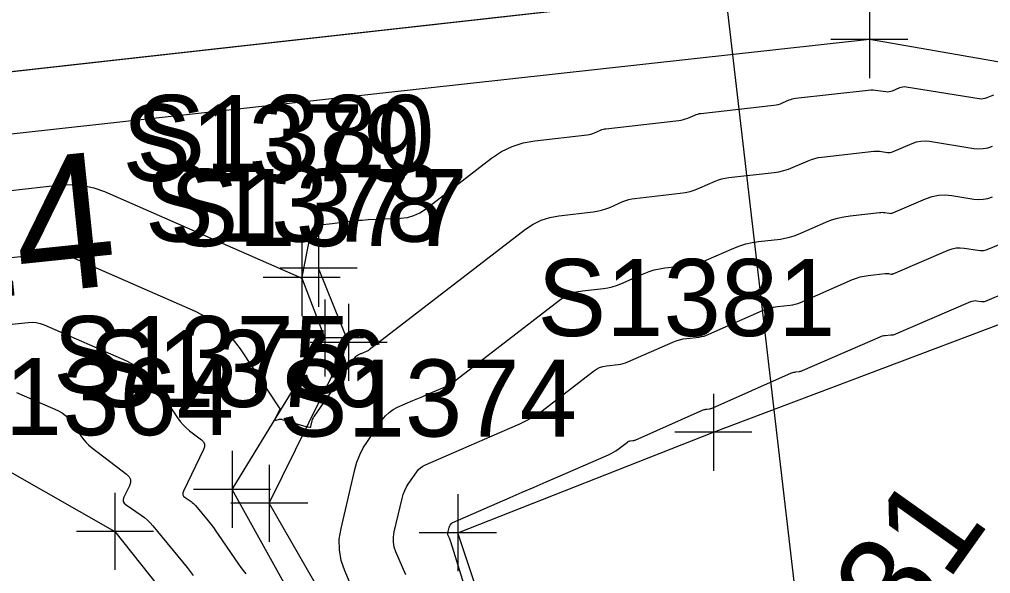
# Model space of a CAD drawing. Extents: x 816928 to 825690, y 436959 to 448212.
# Drawn here: x 818841.5 to 818891.9, y 445163.6 to 445192.4 of the extents above; entities that cross this region are included whole.
import ezdxf

# ---------------------------------------------------------------- set-up
doc = ezdxf.new("R2010")
doc.units = 0
for name, color, linetype in [('SURVEY - CONTOURS - Index with Text', 7, 'Continuous'), ('SURVEY - CONTOURS - Intermediate with optional Text', 7, 'Continuous'), ('SURVEY - DRAINAGE - Bridge Hydraulic Data - Points - Locators', 7, 'Continuous'), ('SURVEY - DRAINAGE - Bridge Hydraulic Data - Points - Numbers', 7, 'Continuous'), ('SURVEY - DRAINAGE - Bridge Hydraulic Data with Text', 7, 'Continuous'), ('SURVEY - DRAINAGE - Bridges Text', 7, 'Continuous'), ('SURVEY - DRAINAGE - Natural Features', 7, 'Continuous'), ('SURVEY - DTM - Breaklines', 7, 'Continuous'), ('SURVEY - DTM - Breaklines - Points - Locators', 7, 'Continuous'), ('SURVEY - DTM - Breaklines - Points - Numbers', 7, 'Continuous'), ('SURVEY - PROPERTY - Parcels', 7, 'Continuous'), ('SURVEY - PROPERTY - ROW Lines', 7, 'Continuous')]:
    doc.layers.add(name, color=color, linetype=linetype)

msp = doc.modelspace()

# ---------------------------------------------------------------- linework, layer by layer
at = {"layer": 'SURVEY - CONTOURS - Index with Text'}
msp.add_lwpolyline([(818840.893, 445183.514), (818843.638, 445183.823), (818844.22, 445183.851), (818844.791, 445183.803), (818845.35, 445183.679), (818845.898, 445183.48), (818856.103, 445179.004), (818856.108, 445179.002), (818856.112, 445178.999), (818856.115, 445178.996), (818856.118, 445178.992), (818856.127, 445178.978), (818856.129, 445178.976), (818856.131, 445178.975), (818856.133, 445178.976), (818856.136, 445178.978), (818856.143, 445178.987), (818856.145, 445178.989), (818856.146, 445178.992), (818856.147, 445178.994), (818856.148, 445178.996), (818856.153, 445179.016), (818856.154, 445179.021), (818856.156, 445179.025), (818856.157, 445179.029), (818856.157, 445179.034), (818856.619, 445181.334), (818856.676, 445181.503), (818856.772, 445181.63), (818856.907, 445181.716), (818857.081, 445181.759), (818857.711, 445181.831), (818857.845, 445181.847), (818857.98, 445181.862), (818858.115, 445181.878), (818858.25, 445181.893), (818858.966, 445181.976), (818859.119, 445181.992), (818859.273, 445182.005), (818859.427, 445182.016), (818859.581, 445182.024), (818861.271, 445182.098), (818861.623, 445182.139), (818861.957, 445182.232), (818862.272, 445182.377), (818862.569, 445182.572), (818865.992, 445185.214), (818866.506, 445185.558), (818867.051, 445185.825), (818867.628, 445186.013), (818868.236, 445186.122), (818870.946, 445186.428), (818871.047, 445186.443), (818871.147, 445186.466), (818871.244, 445186.496), (818871.34, 445186.534), (818871.649, 445186.67), (818871.715, 445186.697), (818871.784, 445186.718), (818871.853, 445186.734), (818871.924, 445186.745), (818875.716, 445187.172), (818875.834, 445187.19), (818875.949, 445187.216), (818876.062, 445187.251), (818876.173, 445187.295), (818876.531, 445187.454), (818876.609, 445187.485), (818876.688, 445187.509), (818876.769, 445187.528), (818876.852, 445187.54), (818880.638, 445187.966), (818880.754, 445187.984), (818880.868, 445188.01), (818880.979, 445188.044), (818881.088, 445188.087), (818881.44, 445188.241), (818881.517, 445188.271), (818881.594, 445188.295), (818881.674, 445188.313), (818881.755, 445188.325), (818885.54, 445188.75), (818885.666, 445188.76), (818885.792, 445188.762), (818885.918, 445188.754), (818886.043, 445188.739), (818886.452, 445188.674), (818886.539, 445188.666), (818886.625, 445188.671), (818886.709, 445188.688), (818886.791, 445188.717), (818887.171, 445188.88), (818887.253, 445188.909), (818887.336, 445188.925), (818887.422, 445188.93), (818887.508, 445188.922), (818891.297, 445188.312), (818891.405, 445188.302), (818891.511, 445188.307), (818891.615, 445188.327), (818891.718, 445188.363), (818892.05, 445188.502)], dxfattribs=at)
at = {"layer": 'SURVEY - CONTOURS - Intermediate with optional Text'}
for points in [[(818840.919, 445180.044), (818842.789, 445180.255), (818843.186, 445180.274), (818843.575, 445180.241), (818843.956, 445180.157), (818844.329, 445180.021), (818850.611, 445177.266), (818851.299, 445176.906), (818851.916, 445176.461), (818852.462, 445175.93), (818852.936, 445175.315), (818854.973, 445172.254), (818854.977, 445172.249), (818854.981, 445172.244), (818854.986, 445172.239), (818854.991, 445172.235), (818855.009, 445172.221), (818855.012, 445172.218), (818855.013, 445172.215), (818855.013, 445172.211), (818855.012, 445172.207), (818854.76, 445171.686), (818854.747, 445171.647), (818854.751, 445171.623), (818854.774, 445171.613), (818854.815, 445171.617), (818854.978, 445171.656), (818855.013, 445171.661), (818855.048, 445171.663), (818855.082, 445171.659), (818855.117, 445171.651), (818856.353, 445171.28), (818856.382, 445171.272), (818856.411, 445171.265), (818856.44, 445171.26), (818856.469, 445171.255), (818856.566, 445171.243), (818856.585, 445171.243), (818856.599, 445171.249), (818856.61, 445171.261), (818856.617, 445171.278), (818856.687, 445171.579), (818856.705, 445171.642), (818856.729, 445171.703), (818856.758, 445171.761), (818856.793, 445171.816), (818858.907, 445174.872), (818858.938, 445174.912), (818858.974, 445174.946), (818859.015, 445174.975), (818859.06, 445174.998), (818859.213, 445175.064), (818859.246, 445175.079), (818859.279, 445175.093), (818859.312, 445175.107), (818859.345, 445175.122), (818859.512, 445175.194), (818859.548, 445175.211), (818859.582, 445175.229), (818859.614, 445175.25), (818859.646, 445175.273), (818867.754, 445181.528), (818868.148, 445181.792), (818868.566, 445181.996), (818869.008, 445182.141), (818869.474, 445182.225), (818871.255, 445182.425), (818871.479, 445182.459), (818871.7, 445182.51), (818871.915, 445182.577), (818872.127, 445182.661), (818872.809, 445182.961), (818872.957, 445183.02), (818873.108, 445183.067), (818873.262, 445183.102), (818873.42, 445183.126), (818875.783, 445183.392), (818876.045, 445183.432), (818876.301, 445183.491), (818876.552, 445183.569), (818876.797, 445183.667), (818877.591, 445184.018), (818877.763, 445184.086), (818877.939, 445184.141), (818878.118, 445184.182), (818878.301, 445184.21), (818880.649, 445184.474), (818880.906, 445184.512), (818881.158, 445184.57), (818881.405, 445184.646), (818881.647, 445184.741), (818882.429, 445185.083), (818882.599, 445185.15), (818882.772, 445185.203), (818882.948, 445185.243), (818883.128, 445185.27), (818885.833, 445185.574), (818885.93, 445185.582), (818886.028, 445185.583), (818886.126, 445185.577), (818886.223, 445185.565), (818886.541, 445185.515), (818886.609, 445185.509), (818886.675, 445185.512), (818886.74, 445185.525), (818886.804, 445185.548), (818887.818, 445185.984), (818888.038, 445186.061), (818888.261, 445186.105), (818888.488, 445186.117), (818888.72, 445186.096), (818891.022, 445185.725), (818891.267, 445185.703), (818891.509, 445185.714), (818891.746, 445185.76), (818891.979, 445185.84)], [(818859.438, 445161.295), (818858.37, 445163.788), (818858.186, 445164.327), (818858.093, 445164.873), (818858.09, 445165.427), (818858.177, 445165.989), (818858.896, 445169.047), (818859.006, 445169.435), (818859.151, 445169.807), (818859.33, 445170.165), (818859.544, 445170.507), (818860.32, 445171.628), (818860.483, 445171.833), (818860.669, 445172.009), (818860.879, 445172.158), (818861.111, 445172.278), (818861.91, 445172.624), (818862.081, 445172.698), (818862.252, 445172.773), (818862.423, 445172.847), (818862.594, 445172.921), (818863.461, 445173.297), (818863.644, 445173.383), (818863.82, 445173.48), (818863.99, 445173.587), (818864.154, 445173.706), (818869.516, 445177.842), (818869.79, 445178.026), (818870.08, 445178.168), (818870.388, 445178.268), (818870.712, 445178.327), (818871.8, 445178.45), (818872.031, 445178.484), (818872.257, 445178.536), (818872.479, 445178.605), (818872.696, 445178.691), (818873.905, 445179.224), (818874.167, 445179.328), (818874.434, 445179.411), (818874.707, 445179.474), (818874.986, 445179.516), (818876.164, 445179.648), (818876.414, 445179.686), (818876.658, 445179.742), (818876.898, 445179.817), (818877.133, 445179.911), (818878.564, 445180.543), (818878.874, 445180.666), (818879.191, 445180.765), (818879.514, 445180.839), (818879.844, 445180.889), (818880.978, 445181.017), (818881.218, 445181.053), (818881.454, 445181.107), (818881.686, 445181.178), (818881.912, 445181.267), (818883.33, 445181.887), (818883.637, 445182.008), (818883.951, 445182.104), (818884.271, 445182.177), (818884.597, 445182.226), (818886.125, 445182.398), (818886.194, 445182.403), (818886.264, 445182.404), (818886.334, 445182.4), (818886.403, 445182.392), (818886.63, 445182.356), (818886.678, 445182.351), (818886.725, 445182.354), (818886.772, 445182.363), (818886.817, 445182.379), (818888.517, 445183.11), (818888.848, 445183.226), (818889.184, 445183.293), (818889.527, 445183.311), (818889.876, 445183.279), (818891.026, 445183.094), (818891.271, 445183.071), (818891.511, 445183.083), (818891.747, 445183.128), (818891.979, 445183.208)], [(818861.536, 445163.582), (818861.029, 445164.764), (818860.942, 445165.02), (818860.898, 445165.279), (818860.896, 445165.541), (818860.938, 445165.808), (818861.345, 445167.54), (818861.405, 445167.75), (818861.483, 445167.952), (818861.58, 445168.145), (818861.696, 445168.331), (818862.105, 445168.922), (818862.199, 445169.04), (818862.307, 445169.142), (818862.428, 445169.228), (818862.563, 445169.298), (818864.426, 445170.106), (818864.825, 445170.279), (818865.224, 445170.452), (818865.624, 445170.625), (818866.023, 445170.798), (818867.464, 445171.424), (818867.768, 445171.567), (818868.061, 445171.727), (818868.343, 445171.906), (818868.615, 445172.103), (818871.278, 445174.157), (818871.431, 445174.26), (818871.595, 445174.34), (818871.768, 445174.396), (818871.95, 445174.429), (818872.562, 445174.498), (818872.692, 445174.518), (818872.819, 445174.547), (818872.944, 445174.586), (818873.066, 445174.634), (818875.391, 445175.658), (818875.569, 445175.729), (818875.752, 445175.786), (818875.939, 445175.829), (818876.129, 445175.858), (818876.757, 445175.928), (818876.89, 445175.948), (818877.02, 445175.978), (818877.148, 445176.018), (818877.273, 445176.068), (818880.055, 445177.298), (818880.241, 445177.372), (818880.432, 445177.431), (818880.626, 445177.476), (818880.824, 445177.506), (818881.479, 445177.579), (818881.618, 445177.6), (818881.754, 445177.631), (818881.887, 445177.672), (818882.018, 445177.724), (818884.727, 445178.907), (818884.921, 445178.983), (818885.119, 445179.045), (818885.321, 445179.091), (818885.528, 445179.122), (818886.417, 445179.222), (818886.458, 445179.225), (818886.5, 445179.225), (818886.542, 445179.223), (818886.583, 445179.218), (818886.718, 445179.196), (818886.747, 445179.194), (818886.775, 445179.195), (818886.803, 445179.201), (818886.83, 445179.21), (818889.692, 445180.441), (818889.894, 445180.512), (818890.099, 445180.553), (818890.308, 445180.563), (818890.52, 445180.544), (818891.221, 445180.431), (818891.37, 445180.418), (818891.516, 445180.425), (818891.66, 445180.452), (818891.801, 445180.501), (818894.369, 445181.583)], [(818864.566, 445163.053), (818863.872, 445165.287), (818863.856, 445165.334), (818863.84, 445165.381), (818863.822, 445165.427), (818863.803, 445165.473), (818863.739, 445165.622), (818863.729, 445165.654), (818863.723, 445165.686), (818863.723, 445165.719), (818863.728, 445165.753), (818863.794, 445166.033), (818863.803, 445166.066), (818863.815, 445166.097), (818863.83, 445166.126), (818863.848, 445166.155), (818863.911, 445166.245), (818863.925, 445166.264), (818863.942, 445166.279), (818863.96, 445166.292), (818863.981, 445166.303), (818866.957, 445167.594), (818867.577, 445167.863), (818868.197, 445168.132), (818868.817, 445168.401), (818869.437, 445168.67), (818872.062, 445169.808), (818872.194, 445169.87), (818872.322, 445169.94), (818872.445, 445170.018), (818872.563, 445170.104), (818873.039, 445170.471), (818873.073, 445170.494), (818873.11, 445170.512), (818873.148, 445170.524), (818873.188, 445170.532), (818873.324, 445170.547), (818873.353, 445170.551), (818873.381, 445170.558), (818873.409, 445170.566), (818873.436, 445170.577), (818876.978, 445172.138), (818877.022, 445172.155), (818877.068, 445172.169), (818877.114, 445172.18), (818877.161, 445172.187), (818877.316, 445172.204), (818877.349, 445172.209), (818877.382, 445172.217), (818877.413, 445172.227), (818877.444, 445172.239), (818881.563, 445174.06), (818881.617, 445174.081), (818881.672, 445174.098), (818881.728, 445174.111), (818881.785, 445174.12), (818881.974, 445174.141), (818882.014, 445174.147), (818882.054, 445174.156), (818882.092, 445174.168), (818882.13, 445174.183), (818886.159, 445175.943), (818886.222, 445175.968), (818886.287, 445175.988), (818886.353, 445176.003), (818886.42, 445176.013), (818886.709, 445176.045), (818886.723, 445176.046), (818886.736, 445176.047), (818886.75, 445176.046), (818886.763, 445176.044), (818886.807, 445176.037), (818886.816, 445176.036), (818886.826, 445176.037), (818886.835, 445176.039), (818886.844, 445176.042), (818890.868, 445177.773), (818890.94, 445177.798), (818891.014, 445177.812), (818891.088, 445177.816), (818891.165, 445177.809), (818891.416, 445177.769), (818891.469, 445177.764), (818891.522, 445177.767), (818891.573, 445177.776), (818891.624, 445177.794), (818895.488, 445179.422)], [(818840.933, 445176.573), (818841.937, 445176.686), (818842.15, 445176.697), (818842.359, 445176.679), (818842.563, 445176.634), (818842.764, 445176.561), (818847.042, 445174.685), (818847.5, 445174.445), (818847.911, 445174.149), (818848.274, 445173.795), (818848.59, 445173.385), (818849.691, 445171.731), (818849.828, 445171.542), (818849.979, 445171.366), (818850.144, 445171.204), (818850.323, 445171.054), (818850.931, 445170.587), (818851.036, 445170.481), (818851.09, 445170.363), (818851.094, 445170.233), (818851.048, 445170.091), (818849.998, 445167.921), (818849.967, 445167.824), (818849.971, 445167.737), (818850.011, 445167.659), (818850.087, 445167.592), (818850.394, 445167.386), (818850.457, 445167.34), (818850.517, 445167.289), (818850.573, 445167.234), (818850.625, 445167.175), (818851.279, 445166.376), (818851.417, 445166.203), (818851.552, 445166.027), (818851.683, 445165.849), (818851.81, 445165.668), (818852.865, 445164.134), (818852.983, 445163.964), (818853.105, 445163.798), (818853.231, 445163.634)], [(818841.342, 445173.038), (818843.473, 445172.104), (818843.701, 445171.984), (818843.905, 445171.836), (818844.086, 445171.66), (818844.244, 445171.456), (818844.718, 445170.743), (818844.826, 445170.595), (818844.944, 445170.458), (818845.073, 445170.331), (818845.213, 445170.214), (818847.051, 445168.801), (818847.178, 445168.672), (818847.244, 445168.529), (818847.249, 445168.371), (818847.193, 445168.199), (818846.909, 445167.614), (818846.871, 445167.494), (818846.876, 445167.386), (818846.926, 445167.291), (818847.02, 445167.207), (818847.814, 445166.674), (818847.979, 445166.554), (818848.134, 445166.423), (818848.279, 445166.281), (818848.414, 445166.128), (818850.193, 445163.952), (818850.302, 445163.816), (818850.409, 445163.677), (818850.512, 445163.536)]]:
    msp.add_lwpolyline(points, dxfattribs=at)
at = {"layer": 'SURVEY - DRAINAGE - Bridge Hydraulic Data - Points - Locators'}
for p, q in [((818885.6, 445193.376), (818885.6, 445189.376)), ((818887.6, 445191.376), (818883.6, 445191.376)), ((818877.5, 445172.98), (818877.5, 445168.98)), ((818879.5, 445170.98), (818875.5, 445170.98)), ((818846.448, 445167.831), (818846.448, 445163.831)), ((818864.238, 445167.76), (818864.238, 445163.76)), ((818848.448, 445165.831), (818844.448, 445165.831)), ((818866.238, 445165.76), (818862.238, 445165.76))]:
    msp.add_line(p, q, dxfattribs=at)
at = {"layer": 'SURVEY - DRAINAGE - Bridge Hydraulic Data with Text'}
for p, q in [((818883.11, 445151.193), (818874.403, 445225.686)), ((818834.683, 445188.997), (818885.355, 445194.671))]:
    msp.add_line(p, q, dxfattribs=at)
for points in [[(818975.535, 445161.489), (818974.654, 445162.222), (818955.542, 445179.169), (818885.6, 445191.376), (818829.741, 445185.211), (818795.23, 445208.399), (818755.569, 445194.059), (818710.632, 445195.982)], [(818784.519, 445183.127), (818807.177, 445189.01), (818822.594, 445179.409), (818846.448, 445165.831), (818864.623, 445142.909), (818851.635, 445125.23), (818852.677, 445121.979), (818854.948, 445121.819)], [(818854.948, 445121.819), (818872.985, 445139.475), (818864.238, 445165.76), (818877.5, 445170.98), (818901.426, 445180.025), (818910.363, 445177.537), (818911.769, 445177.181)]]:
    msp.add_lwpolyline(points, dxfattribs=at)
at = {"layer": 'SURVEY - DRAINAGE - Natural Features'}
msp.add_lwpolyline([(818976.92, 445167.021), (818959.968, 445184.233), (818885.355, 445194.671), (818834.683, 445188.997), (818798.356, 445212.301), (818757.037, 445198.917), (818710.514, 445201.057)], dxfattribs=at)
at = {"layer": 'SURVEY - DTM - Breaklines'}
for points in [[(818855.139, 445123.73), (818868.422, 445142.981), (818854.455, 445167.294), (818858.57, 445175.647), (818857.013, 445179.498)], [(818853.152, 445123.838), (818866.552, 445142.733), (818852.525, 445168.017), (818857.339, 445175.88), (818856.138, 445179.015)]]:
    msp.add_lwpolyline(points, dxfattribs=at)
at = {"layer": 'SURVEY - DTM - Breaklines - Points - Locators'}
for p, q in [((818857.013, 445181.498), (818857.013, 445177.498)), ((818856.138, 445181.015), (818856.138, 445177.015)), ((818859.013, 445179.498), (818855.013, 445179.498)), ((818858.138, 445179.015), (818854.138, 445179.015)), ((818857.339, 445177.88), (818857.339, 445173.88)), ((818858.57, 445177.647), (818858.57, 445173.647)), ((818859.339, 445175.88), (818855.339, 445175.88)), ((818860.57, 445175.647), (818856.57, 445175.647)), ((818852.525, 445170.017), (818852.525, 445166.017)), ((818854.455, 445169.294), (818854.455, 445165.294)), ((818854.525, 445168.017), (818850.525, 445168.017)), ((818856.455, 445167.294), (818852.455, 445167.294))]:
    msp.add_line(p, q, dxfattribs=at)
at = {"layer": 'SURVEY - PROPERTY - Parcels'}
msp.add_arc((819561.099, 444735.998), 763, 144.598464, 158.728454, dxfattribs=at)
at = {"layer": 'SURVEY - PROPERTY - ROW Lines'}
msp.add_arc((819561.099, 444735.998), 763, 144.598464, 158.728454, dxfattribs=at)
msp.add_arc((819561.099, 444735.998), 763, 144.598464, 158.728454, dxfattribs=at)

# ---------------------------------------------------------------- texts
at = {"layer": 'SURVEY - DRAINAGE - Bridge Hydraulic Data - Points - Numbers'}
for s, p in [('S1381', (818868.37, 445175.98)), ('S1364', (818837.16, 445170.831)), ('S1374', (818854.95, 445170.76))]:
    msp.add_text(s, height=4, dxfattribs=at).set_placement(p)
at = {"layer": 'SURVEY - DRAINAGE - Bridge Hydraulic Data with Text'}
msp.add_text('L4', height=7, rotation=5.9237, dxfattribs=at).set_placement((818836.366, 445177.584))
at = {"layer": 'SURVEY - DRAINAGE - Bridges Text'}
msp.add_text('56+99.31', height=5, rotation=54.5985, dxfattribs=at).set_placement((818875.551, 445143.336))
at = {"layer": 'SURVEY - DTM - Breaklines - Points - Numbers'}
for s, p in [('S1380', (818847.552, 445184.498)), ('S1379', (818846.834, 445184.015)), ('S1378', (818848.004, 445180.88)), ('S1377', (818849.282, 445180.647)), ('S1375', (818843.238, 445173.017)), ('S1376', (818845.057, 445172.294))]:
    msp.add_text(s, height=4, dxfattribs=at).set_placement(p)

doc.saveas('drawing.dxf')
